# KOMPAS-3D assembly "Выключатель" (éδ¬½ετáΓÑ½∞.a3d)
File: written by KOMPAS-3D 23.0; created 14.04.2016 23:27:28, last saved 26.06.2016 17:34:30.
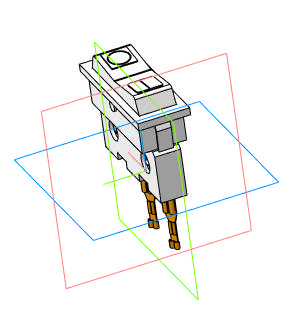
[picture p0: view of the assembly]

Document properties: Автор: Аня; Полное имя файла: C:\Users\zyrianova_ae\Desktop\Задание_колледж\Модели\Выключатель.a3d

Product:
- Component [detail]: Корпус  | Масса: 0.022379; Автор: Аня; source file: Корпус выключателя .m3d
- Component [detail]: Кнопка  | Масса: 0.010375; Автор: Аня; source file: Кнопка выключателя.m3d
- Component [detail]: Пластина  | Масса: 0.000337; Автор: Аня; source file: Пластина выключателя.m3d
- Component [detail]: Пяточка  | Масса: 0.000132; Автор: Аня; source file: Пяточка.m3d
- Component [detail]: Пружина  | Масса: 0.000028; Автор: Аня; source file: Пружина выключателя.m3d
- Component [detail]: Контакт  | Масса: 0.000081; Автор: Аня; source file: Контакт папа 1.m3d
- Component [detail]: Графитный контакт  | qty 2  | Масса: 0.000017; Автор: Аня; source file: Графитный контакт.m3d
- Component [detail]: Контакт  | Масса: 0.000122; Автор: Аня; source file: Контакт папа 2.m3d
- Component [detail]: Контакт  | qty 2  | Масса: 0.000134; Автор: Аня; source file: Контакт мама.m3d
- Part/product: Выключатель
    Масса: 0.033755

Referenced files in C:\Users\zyrianova_ae\Desktop\Задание_колледж\Модели\: Корпус выключателя .m3d, Кнопка выключателя.m3d, Пластина выключателя.m3d, Пяточка.m3d, Пружина выключателя.m3d, Контакт папа 1.m3d, Графитный контакт.m3d, Контакт папа 2.m3d, Контакт мама.m3d
Referenced files in T:\ОИТОД\Электрическая мясорубка\Электрическая мясорубка\: Графитный контакт.m3d, Контакт мама.m3d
